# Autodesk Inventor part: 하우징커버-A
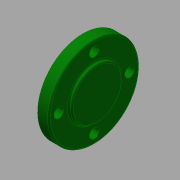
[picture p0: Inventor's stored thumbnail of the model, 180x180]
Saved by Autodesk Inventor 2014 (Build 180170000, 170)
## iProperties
Created: 2018-01
Part Number: 하우징커버-A
Material: 알루미늄 6061
Document SubType Name: Modeling
Designer: mduedu
Density: 1 g/cm^3
Appearance: 진녹색
Author: mduedu
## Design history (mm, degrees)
sketch "스케치1"
  geometry: C1 r 16 at (0, 0); 1 further point
  constraints: 1 centre point, 1 coincident
  dimensions: "d0" = 32 diameter of C1
extrude "돌출1" new body sketch "스케치1" distance "d1" = 4; taper "d2" = 0 deg
sketch "스케치2"
  geometry: C1 r 9 at (0, 0); 1 further point
  constraints: 1 centre point, 1 coincident
  dimensions: "d3" = 18 diameter of C1
extrude "돌출2" join sketch "스케치2" distance "d4" = 1; taper "d5" = 0 deg
fillet "모깎기1" dims "d6" = 0.5
fillet "모깎기2" dims "d7" = 0.5
sketch "스케치3" dims "d8" = 25
  geometry: 6 further points
  constraints: 2 vertical alignment, 1 coincident, 7 other
  dimensions: "d11" = 360 deg dimension on point (0, 0) point (0, 12.5) (derived)
sketch "스케치4"
  geometry: 4 further points
  constraints: 4 other
hole "구멍1" sketch "스케치4" at (-12.5, 0), (0, -12.5), (12.5, 0), (0, 12.5) diameter "d13" = 3.4; stored, may be unused: countersink angle "d17" = 90 deg, drill point angle "d19" = 0 deg; dims "d14" = 6, "d15" = 4, "d16" = 2, "d18" = 8
node "솔리드1"
